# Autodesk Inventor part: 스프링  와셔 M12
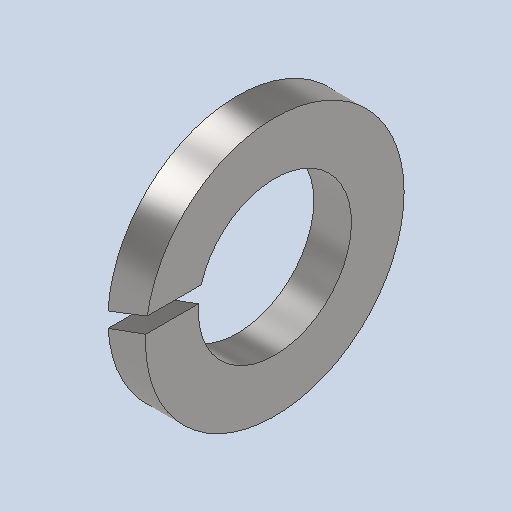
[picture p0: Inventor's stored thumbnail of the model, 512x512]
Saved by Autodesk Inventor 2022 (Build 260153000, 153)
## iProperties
Created: 2024-07
Part Number: 스프링  와셔 M12
Material: 강철, 연강
Description: 스프링 잠금 와셔
Document SubType Name: Modeling
Designer: PC-01
Density: 7.85 g/cm^3
Appearance: 기본값
Author: jhkim
Sending System: Autodesk Inventor 2025
Preprocessor: ST-DEVELOPER v20
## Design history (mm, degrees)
feature "Solid1"
node "솔리드1"
